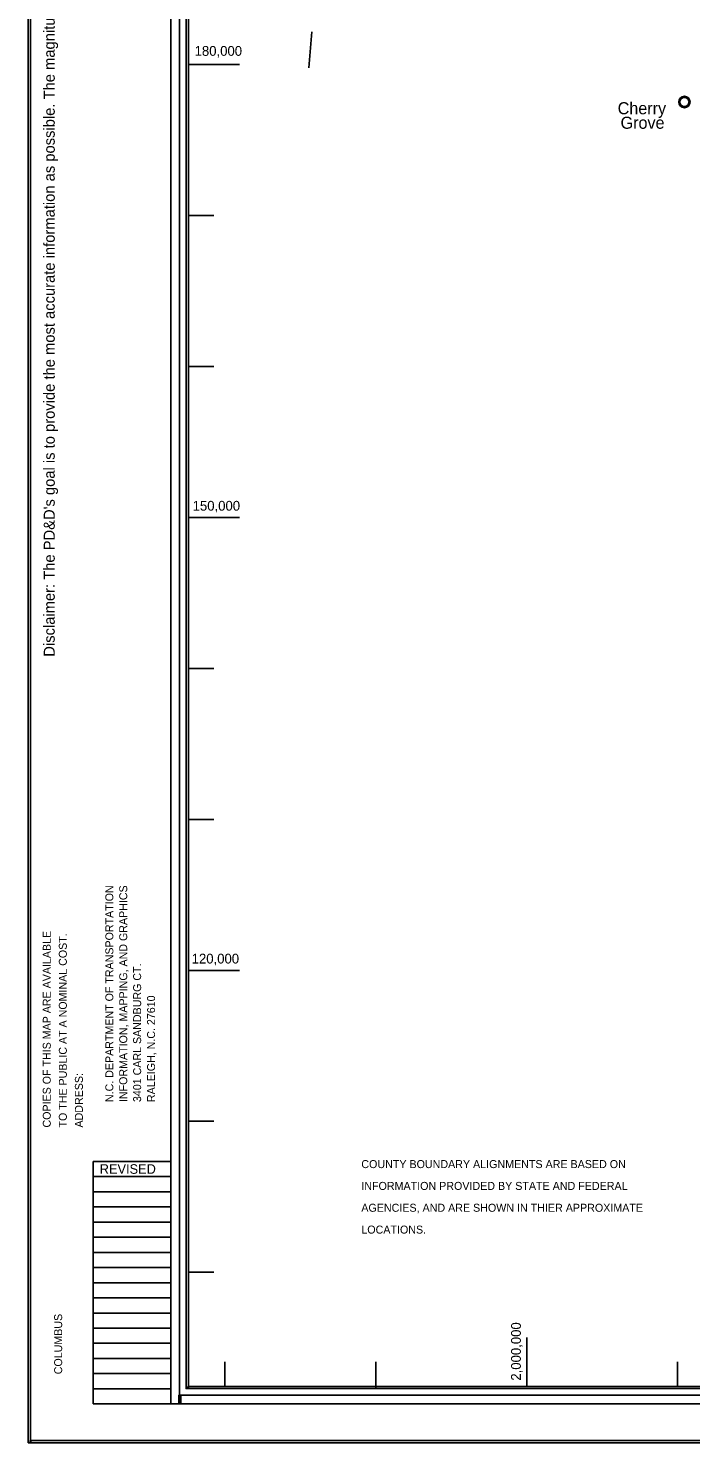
# Model space of a CAD drawing. Extents: x 5197761 to 5514561, y 1890130 to 2080942.
# Drawn here: x 5197761 to 5241653, y 1890130 to 1983827 of the extents above; entities that cross this region are included whole.
import ezdxf

# ---------------------------------------------------------------- set-up
doc = ezdxf.new("R2010")
doc.units = 0
for name, color, linetype in [('Exist Civil Demographics Community CELL', 7, 'Continuous'), ('Exist Civil Demographics Community Label', 7, 'Continuous'), ('Map Preparation Base Disclaimer Boundary CELL', 7, 'Continuous'), ('Map Preparation Base StatePlane Tick Label', 7, 'Continuous'), ('Map Preparation Base StatePlane Tick Mark', 7, 'Continuous'), ('Map Preparation Border Address Label', 7, 'Continuous'), ('Map Preparation Border Antique Large Shape', 7, 'Continuous'), ('Map Preparation Border Antique Small Shape', 7, 'Continuous'), ('Map Preparation Border Black Inside Shape', 7, 'Continuous'), ('Map Preparation Border Black Middle Shape', 7, 'Continuous'), ('Map Preparation Border Black Outside Shape', 7, 'Continuous'), ('Map Preparation Border County Name Left Corner Label', 7, 'Continuous'), ('Map Preparation Border Disclaimer', 7, 'Continuous'), ('Map Preparation Border Revised Sign Off', 7, 'Continuous'), ('Map Preparation Destination Label', 7, 'Continuous')]:
    doc.layers.add(name, color=color, linetype=linetype)

msp = doc.modelspace()

# ---------------------------------------------------------------- linework, layer by layer
at = {"layer": 'Exist Civil Demographics Community CELL'}
msp.add_lwpolyline([(5240925, 1978993), (5240929, 1979016), (5240936, 1979042), (5240948, 1979071), (5240959, 1979094), (5240973, 1979117), (5240988, 1979137), (5241003, 1979155), (5241022, 1979173), (5241044, 1979191), (5241066, 1979206), (5241085, 1979218), (5241105, 1979227), (5241127, 1979237), (5241150, 1979244), (5241167, 1979248), (5241187, 1979251), (5241203, 1979254), (5241228, 1979255), (5241246, 1979255), (5241269, 1979254), (5241288, 1979251), (5241308, 1979247), (5241328, 1979241), (5241349, 1979234), (5241375, 1979222), (5241400, 1979208), (5241421, 1979194), (5241441, 1979178), (5241455, 1979165), (5241471, 1979148), (5241487, 1979129), (5241499, 1979110), (5241511, 1979090), (5241521, 1979070), (5241529, 1979050), (5241536, 1979030), (5241541, 1979011), (5241545, 1978987), (5241548, 1978968), (5241549, 1978944), (5241548, 1978921), (5241546, 1978898), (5241542, 1978877), (5241535, 1978852), (5241528, 1978829), (5241519, 1978808), (5241506, 1978784), (5241493, 1978763), (5241479, 1978744), (5241462, 1978725), (5241441, 1978705), (5241421, 1978689), (5241401, 1978675), (5241384, 1978665), (5241356, 1978652), (5241328, 1978641), (5241304, 1978635), (5241278, 1978630), (5241260, 1978628), (5241242, 1978627), (5241220, 1978627), (5241202, 1978629), (5241180, 1978632), (5241156, 1978637), (5241138, 1978642), (5241117, 1978650), (5241099, 1978658), (5241083, 1978667), (5241056, 1978683), (5241034, 1978700), (5241014, 1978718), (5240996, 1978738), (5240983, 1978753), (5240971, 1978770), (5240955, 1978798), (5240948, 1978813), (5240941, 1978829), (5240931, 1978861), (5240925, 1978890), (5240922, 1978910), (5240921, 1978936), (5240921, 1978954), (5240923, 1978980)], close=True, dxfattribs=at)
for centre, radius in [((5241235, 1978944), 377), ((5241234, 1978945), 307)]:
    msp.add_circle(centre, radius, dxfattribs=at)
at = {"layer": 'Map Preparation Base StatePlane Tick Mark'}
for p, q in [((5208366, 1981420), (5211764, 1981420)), ((5208366, 1971420), (5210065, 1971420)), ((5208366, 1961420), (5210065, 1961420)), ((5208366, 1951420), (5211764, 1951420)), ((5208366, 1941420), (5210065, 1941420)), ((5208366, 1931420), (5210065, 1931420)), ((5208366, 1921420), (5211764, 1921420)), ((5208366, 1911420), (5210065, 1911420)), ((5208366, 1901420), (5210065, 1901420)), ((5230787, 1893858), (5230787, 1897109)), ((5210787, 1893858), (5210787, 1895484)), ((5220787, 1893712), (5220787, 1895484)), ((5240787, 1893858), (5240787, 1895484))]:
    msp.add_line(p, q, dxfattribs=at)
at = {"layer": 'Map Preparation Border Antique Large Shape'}
msp.add_lwpolyline([(5197907, 2074783), (5207205, 2074783), (5207205, 1892697), (5512539, 1892697), (5512539, 2072359), (5207205, 2072359), (5207205, 2074783), (5514414, 2074783), (5514414, 1890276), (5197907, 1890276)], close=True, dxfattribs=at)
at = {"layer": 'Map Preparation Border Antique Small Shape'}
msp.add_lwpolyline([(5207791, 2071720), (5208220, 2071720), (5208220, 1893712), (5511524, 1893712), (5511524, 2071291), (5208220, 2071291), (5208220, 2071720), (5207791, 2071720), (5511953, 2071720), (5511953, 1893283), (5208220, 1893283), (5207791, 1893283)], close=True, dxfattribs=at)
at = {"layer": 'Map Preparation Border Black Inside Shape'}
for points in [[(5208220, 2071291), (5511524, 2071291), (5511524, 1893712), (5208366, 1893712), (5208366, 1893858), (5511378, 1893858), (5511378, 2071145), (5208366, 2071145), (5208366, 1893858), (5208366, 1893712), (5208220, 1893712), (5208220, 1893858)], [(5208339, 1893856), (5208386, 1893856), (5208386, 1893714), (5208339, 1893714)]]:
    msp.add_lwpolyline(points, close=True, dxfattribs=at)
at = {"layer": 'Map Preparation Border Black Middle Shape'}
for points in [[(5207205, 2072359), (5512539, 2072359), (5512539, 1892697), (5511953, 1892697), (5207791, 1892697), (5207791, 1893283), (5511953, 1893283), (5511953, 2071720), (5207791, 2071720), (5207791, 1892697), (5207205, 1892697)], [(5207875, 1893274), (5207735, 1893274), (5207735, 1892706), (5207877, 1892706)]]:
    msp.add_lwpolyline(points, close=True, dxfattribs=at)
at = {"layer": 'Map Preparation Border Black Outside Shape'}
for points in [[(5197761, 2074930), (5514561, 2074930), (5514561, 1890130), (5197907, 1890130), (5197907, 1890276), (5514414, 1890276), (5514414, 2074783), (5197907, 2074783), (5197907, 1890130), (5197761, 1890130)], [(5197885, 1890274), (5197932, 1890274), (5197932, 1890132), (5197885, 1890132)]]:
    msp.add_lwpolyline(points, close=True, dxfattribs=at)
at = {"layer": 'Map Preparation Border Revised Sign Off'}
for p, q in [((5202051, 1908764), (5207205, 1908764)), ((5202051, 1907760), (5207205, 1907760)), ((5202051, 1906756), (5207205, 1906756)), ((5202051, 1905752), (5207205, 1905752)), ((5202051, 1904747), (5207205, 1904747)), ((5202051, 1903743), (5207205, 1903743)), ((5202051, 1902739), (5207205, 1902739)), ((5202051, 1901735), (5207205, 1901735)), ((5202051, 1900731), (5207205, 1900731)), ((5202051, 1899726), (5207205, 1899726)), ((5202051, 1898722), (5207205, 1898722)), ((5202051, 1897718), (5207205, 1897718)), ((5202051, 1896714), (5207205, 1896714)), ((5202051, 1895710), (5207205, 1895710)), ((5202051, 1894705), (5207205, 1894705)), ((5202051, 1893701), (5207205, 1893701)), ((5202051, 1892697), (5207205, 1892697))]:
    msp.add_line(p, q, dxfattribs=at)
msp.add_lwpolyline([(5202051, 1908764), (5202051, 1892697)], dxfattribs=at)
at = {"layer": 'Map Preparation Destination Label'}
msp.add_line((5216345, 1981207), (5216543, 1983590), dxfattribs=at)

# ---------------------------------------------------------------- texts
at = {"layer": 'Exist Civil Demographics Community Label'}
for s, p in [('Cherry', (5236812, 1978131)), ('Grove', (5237004, 1977171))]:
    msp.add_text(s, height=800, dxfattribs=at).set_placement(p)
at = {"layer": 'Map Preparation Base Disclaimer Boundary CELL'}
for s, p in [('COUNTY BOUNDARY ALIGNMENTS ARE BASED ON', (5219828, 1908322)), ('INFORMATION PROVIDED BY STATE AND FEDERAL', (5219828, 1906876)), ('AGENCIES, AND ARE SHOWN IN THIER APPROXIMATE', (5219828, 1905429)), ('LOCATIONS.', (5219828, 1903982))]:
    msp.add_text(s, height=530, dxfattribs=at).set_placement(p)
at = {"layer": 'Map Preparation Base StatePlane Tick Label'}
for s, p in [('180,000', (5208783, 1982003)), ('150,000', (5208652, 1951872)), ('120,000', (5208587, 1921872))]:
    msp.add_text(s, height=650, dxfattribs=at).set_placement(p)
msp.add_text('2,000,000', height=650, rotation=90, dxfattribs=at).set_placement((5230400, 1894241))
at = {"layer": 'Map Preparation Border Address Label'}
for s, height, p in [('N.C. DEPARTMENT OF TRANSPORTATION', 527.96, (5203395, 1912696)), ('INFORMATION, MAPPING, AND GRAPHICS', 527.96, (5204317, 1912696)), ('COPIES OF THIS MAP ARE AVAILABLE', 527.96, (5199250, 1911010)), ('TO THE PUBLIC AT A NOMINAL COST.', 527.96, (5200314, 1911010)), ('3401 CARL SANDBURG CT.', 527.96, (5205238, 1912696)), ('RALEIGH, N.C. 27610', 527.96, (5206160, 1912696)), ('ADDRESS:', 528, (5201378, 1911010))]:
    msp.add_text(s, height=height, rotation=90, dxfattribs=at).set_placement(p)
at = {"layer": 'Map Preparation Border County Name Left Corner Label'}
msp.add_text('  COLUMBUS  ', height=527.96, rotation=90, dxfattribs=at).set_placement((5200005, 1894272))
at = {"layer": 'Map Preparation Border Disclaimer'}
msp.add_text("Disclaimer: The PD&D's goal is to provide the most accurate information as possible. The magnitude of the data prevents any guarantee of accuracy or completeness. If you find any information that is incorrect, please send your request to the PD&D Section.", height=730, rotation=90, dxfattribs=at).set_placement((5199514, 1942196))
at = {"layer": 'Map Preparation Border Revised Sign Off'}
msp.add_text('REVISED', height=633.5, rotation=360, dxfattribs=at).set_placement((5202495, 1907944))

doc.saveas('drawing.dxf')
